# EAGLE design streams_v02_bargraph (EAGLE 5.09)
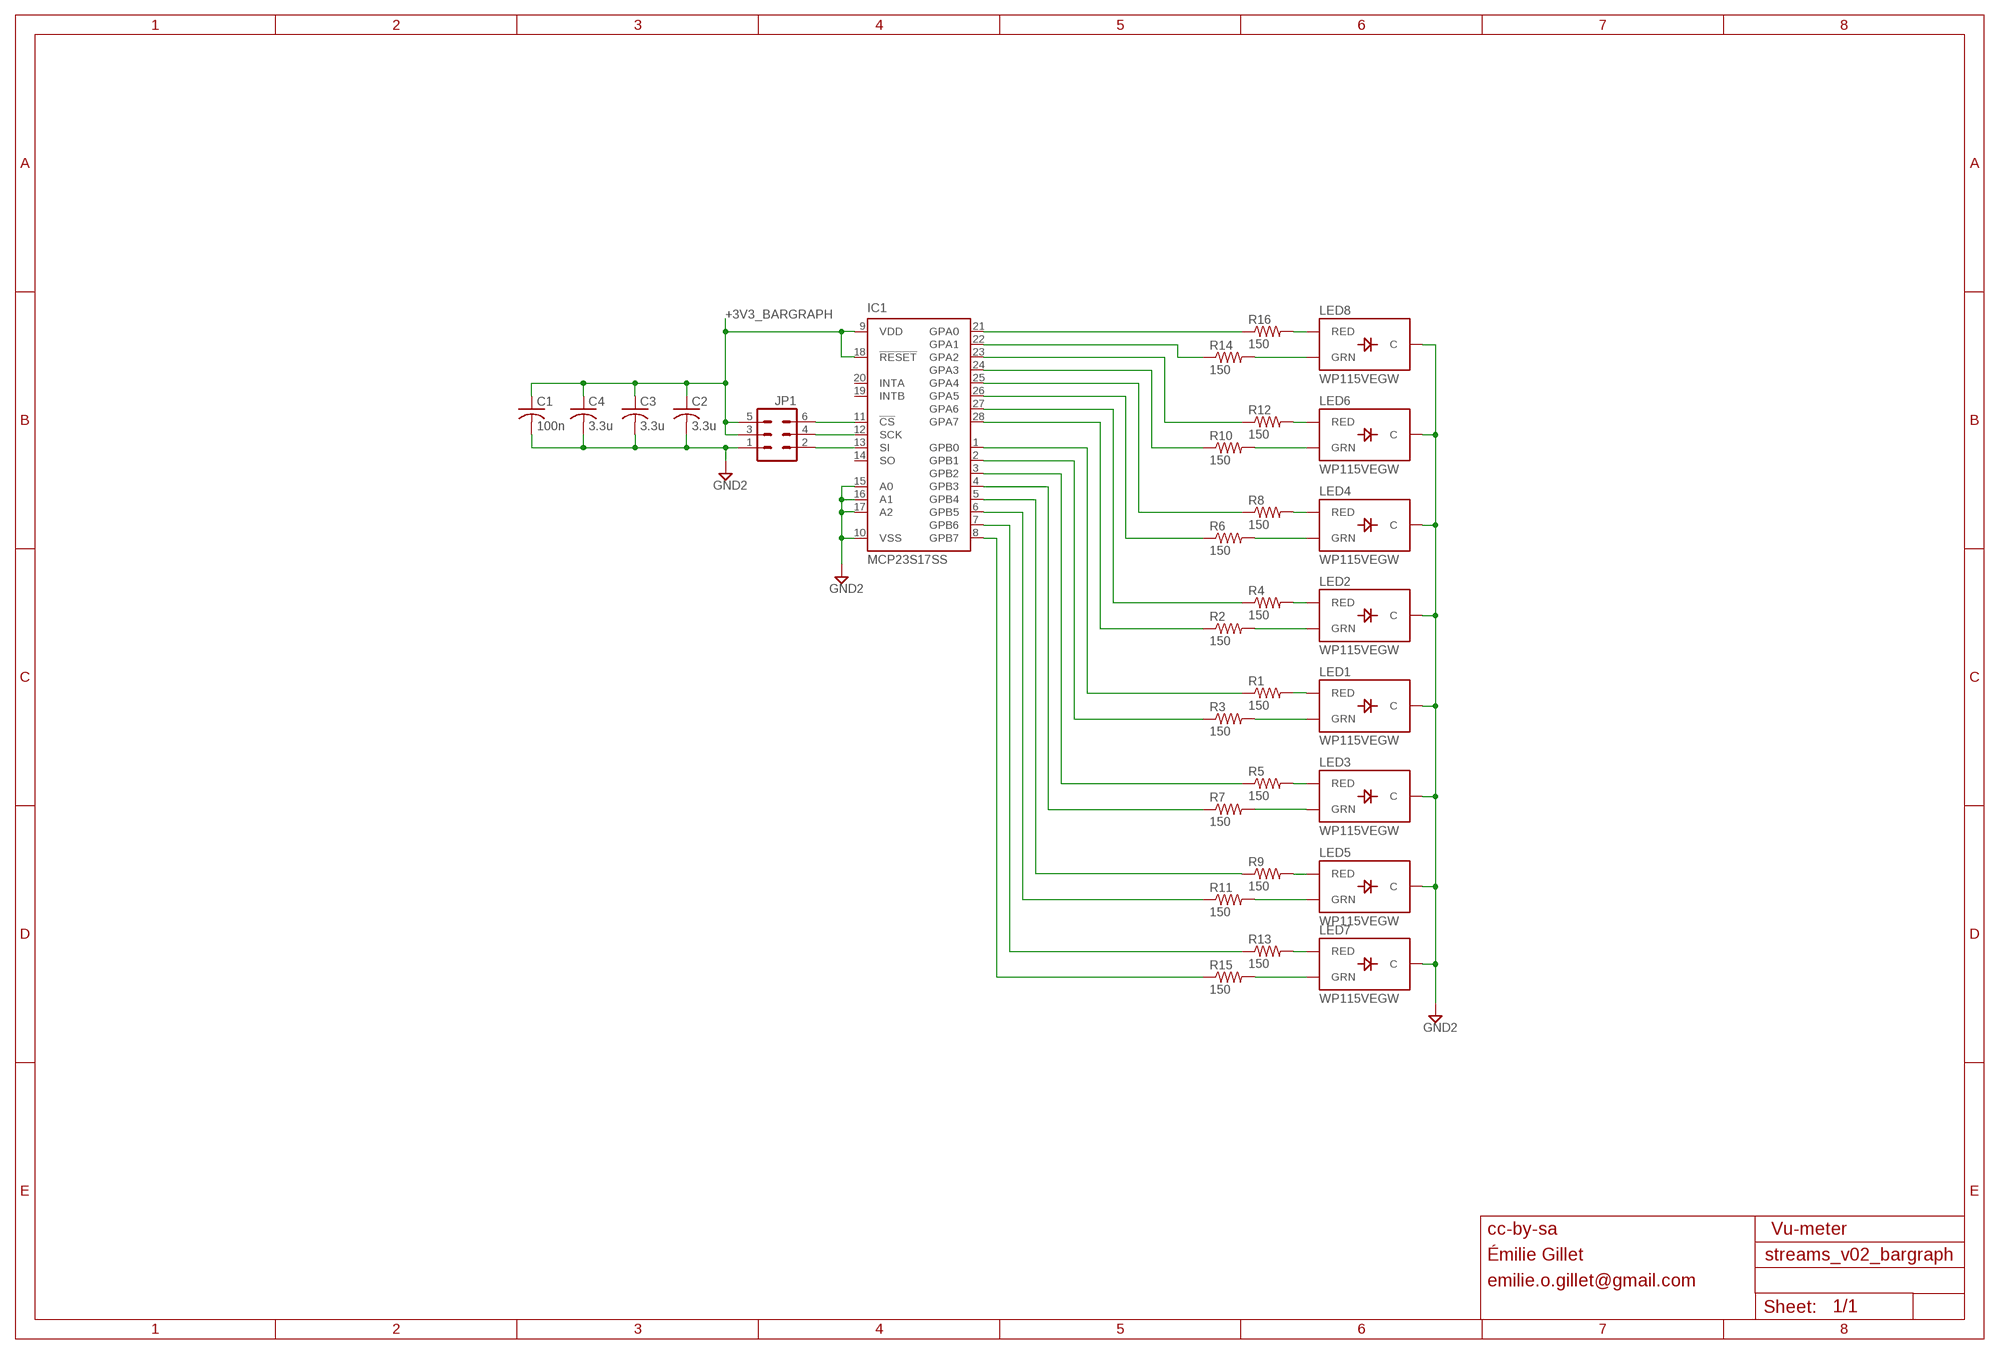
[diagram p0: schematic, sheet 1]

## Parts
C1  100n  C-USC0603  [C0603]
C2  3.3u  C-USC0603  [C0603]
C3  3.3u  C-USC0603  [C0603]
C4  3.3u  C-USC0603  [C0603]
IC1  MCP23S17SS  [SSOP28]
JP1  M03X2  [2X3]
LED1  WP115VEGW  LED-BICOLOR-THROUGHHOLE  [LED-BICOLOR-THROUGHHOLE]
LED2  WP115VEGW  LED-BICOLOR-THROUGHHOLE  [LED-BICOLOR-THROUGHHOLE]
LED3  WP115VEGW  LED-BICOLOR-THROUGHHOLE  [LED-BICOLOR-THROUGHHOLE]
LED4  WP115VEGW  LED-BICOLOR-THROUGHHOLE  [LED-BICOLOR-THROUGHHOLE]
LED5  WP115VEGW  LED-BICOLOR-THROUGHHOLE  [LED-BICOLOR-THROUGHHOLE]
LED6  WP115VEGW  LED-BICOLOR-THROUGHHOLE  [LED-BICOLOR-THROUGHHOLE]
LED7  WP115VEGW  LED-BICOLOR-THROUGHHOLE  [LED-BICOLOR-THROUGHHOLE]
LED8  WP115VEGW  LED-BICOLOR-THROUGHHOLE  [LED-BICOLOR-THROUGHHOLE]
R1  150  R-US_R0603  [R0603]
R2  150  R-US_R0603  [R0603]
R3  150  R-US_R0603  [R0603]
R4  150  R-US_R0603  [R0603]
R5  150  R-US_R0603  [R0603]
R6  150  R-US_R0603  [R0603]
R7  150  R-US_R0603  [R0603]
R8  150  R-US_R0603  [R0603]
R9  150  R-US_R0603  [R0603]
R10  150  R-US_R0603  [R0603]
R11  150  R-US_R0603  [R0603]
R12  150  R-US_R0603  [R0603]
R13  150  R-US_R0603  [R0603]
R14  150  R-US_R0603  [R0603]
R15  150  R-US_R0603  [R0603]
R16  150  R-US_R0603  [R0603]

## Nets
+3V3_BARGRAPH: C1.1 C2.1 C3.1 C4.1 IC1.9(VDD) IC1.18(!RESET) JP1.3 JP1.5
GND2: C1.2 C2.2 C3.2 C4.2 IC1.10(VSS) IC1.15(A0) IC1.16(A1) IC1.17(A2) JP1.1 LED1.2(C) LED2.2(C) LED3.2(C) LED4.2(C) LED5.2(C) LED6.2(C) LED7.2(C) LED8.2(C)
N$1: IC1.11(!CS) JP1.6
N$2: IC1.12(SCK) JP1.4
N$3: LED1.3(RED) R1.2
N$4: IC1.13(SI) JP1.2
N$12: LED1.1(GRN) R3.2
N$21: LED3.3(RED) R5.2
N$22: LED3.1(GRN) R7.2
N$30: LED5.3(RED) R9.2
N$31: LED5.1(GRN) R11.2
N$32: LED7.3(RED) R13.2
N$33: LED7.1(GRN) R15.2
N$34: LED8.3(RED) R16.2
N$35: LED8.1(GRN) R14.2
N$36: LED6.3(RED) R12.2
N$37: LED6.1(GRN) R10.2
N$38: LED4.3(RED) R8.2
N$39: LED4.1(GRN) R6.2
N$40: LED2.3(RED) R4.2
N$41: LED2.1(GRN) R2.2
N$42: IC1.27(GPA6) R4.1
N$44: IC1.28(GPA7) R2.1
N$48: IC1.1(GPB0) R1.1
N$49: IC1.2(GPB1) R3.1
N$50: IC1.21(GPA0) R16.1
N$52: IC1.22(GPA1) R14.1
N$53: IC1.23(GPA2) R12.1
N$54: IC1.24(GPA3) R10.1
N$55: IC1.25(GPA4) R8.1
N$57: IC1.26(GPA5) R6.1
N$58: IC1.3(GPB2) R5.1
N$59: IC1.4(GPB3) R7.1
N$60: IC1.5(GPB4) R9.1
N$61: IC1.6(GPB5) R11.1
N$62: IC1.7(GPB6) R13.1
N$63: IC1.8(GPB7) R15.1
Unconnected: IC1.14(SO) IC1.19(INTB) IC1.20(INTA)

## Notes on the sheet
- cc-by-sa | Vu-meter
- Émilie Gillet
- emilie.o.gillet@gmail.com

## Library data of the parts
C1-C4 = rcl:C-US: CAPACITOR, American symbol
IC1 = microchip:MCP23S17: http://ww1.microchip.com/downloads/en/DeviceDoc/21952a.pdf Source: http://ww1.microchip.com/downloads/en/DeviceDoc/21952a.pdf
JP1 = og-header:M03X2: PIN HEADER
LED1-LED8 = og-leds:LED-BICOLOR-THROUGHHOLE
R1-R16 = rcl:R-US_: RESISTOR, American symbol

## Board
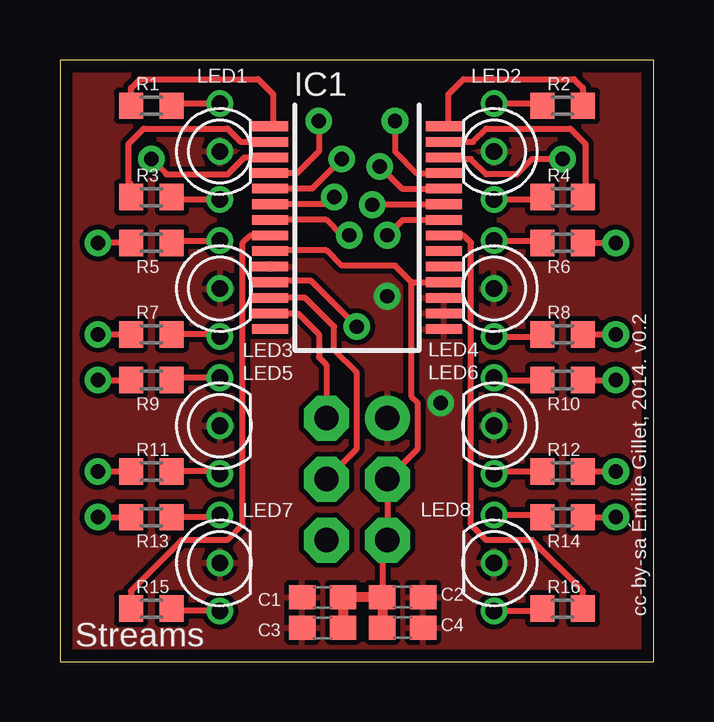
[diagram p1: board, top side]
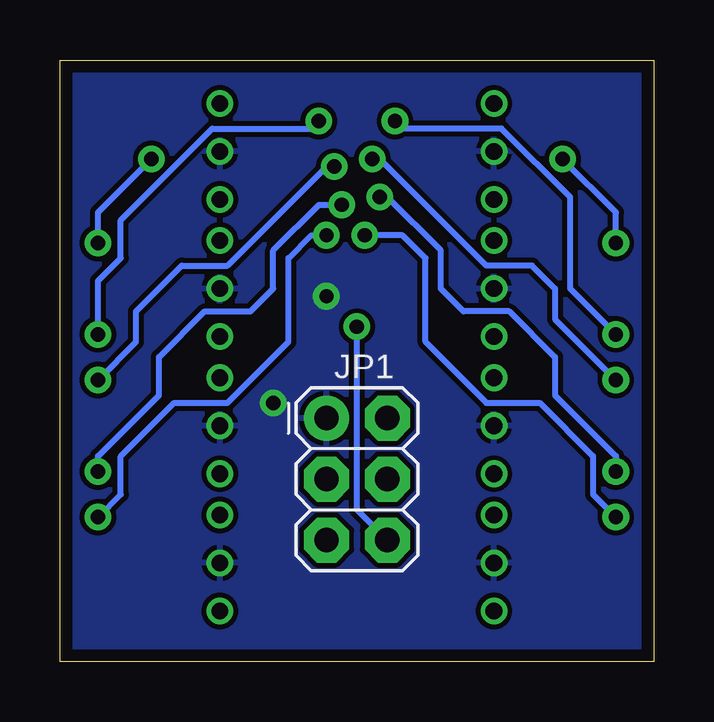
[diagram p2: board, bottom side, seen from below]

Size 24.77 x 25.08 mm. Coordinates in mm from the lower left corner, seen from the top.
Outline: 0,25.08 0,0 24.77,0 24.77,25.08 0,25.08
Copper layers (1*16): Top 0.035mm / dielectric 1.5mm / Bottom 0.035mm
Design rules "PCBCart-Standard": minimum track width 8mil, minimum drill 0.4mm, track to track 8mil, track to pad 8mil, pad to pad 8mil, via to via 8mil, smd to smd 8mil, copper to edge 20mil, drill to drill 8mil, minimum pad ring 8mil, minimum via ring 10mil, stop-mask expansion 3mil, vias tented up to drill 25mil, thermal gap 8mil

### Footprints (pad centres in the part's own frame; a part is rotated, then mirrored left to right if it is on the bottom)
C0603 = smd 1.1 x 1: 1 -0.85,0; 2 0.85,0
SSOP28 = smd 0.4 x 1.5: 1 -4.225,-3.625; 2 -3.575,-3.625; 3 -2.925,-3.625; 4 -2.275,-3.625; 5 -1.625,-3.625; 6 -0.975,-3.625; 7 -0.325,-3.625; 8 0.325,-3.625; 9 0.975,-3.625; 10 1.625,-3.625; 11 2.275,-3.625; 12 2.925,-3.625; 13 3.575,-3.625; 14 4.225,-3.625; 15 4.225,3.625; 16 3.575,3.625; 17 2.925,3.625; 18 2.275,3.625; 19 1.625,3.625; 20 0.975,3.625; 21 0.325,3.625; 22 -0.325,3.625; 23 -0.975,3.625; 24 -1.625,3.625; 25 -2.275,3.625; 26 -2.925,3.625; 27 -3.575,3.625; 28 -4.225,3.625
2X3 = drill 1.016 pad 1.88 round: 1 -2.54,-1.27 | drill 1.016 pad 1.88 octagon: 2 -2.54,1.27; 3 0,-1.27; 4 0,1.27; 5 2.54,-1.27; 6 2.54,1.27
LED-BICOLOR-THROUGHHOLE = drill 0.7 round: 1 -2,0; 2 0,0; 3 2,0
R0603 = smd 1 x 1.1: 1 -0.85,0; 2 0.85,0

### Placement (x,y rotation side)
C1  10.95,2.7 180 top
C2  14.29,2.7 0 top
C3  10.95,1.43 180 top
C4  14.29,1.43 0 top
IC1  12.38,18.1 270 top
JP1  12.38,7.62 270 bottom
LED1  6.67,21.27 90 top
LED2  18.1,21.27 270 top
LED3  6.67,15.56 90 top
LED4  18.1,15.56 270 top
LED5  6.67,9.84 90 top
LED6  18.1,9.84 270 top
LED7  6.67,4.13 90 top
LED8  18.1,4.13 270 top
R1  3.81,23.18 0 top
R2  20.95,23.18 180 top
R3  3.81,19.37 0 top
R4  20.95,19.37 180 top
R5  3.81,17.46 0 top
R6  20.95,17.46 180 top
R7  3.81,13.65 0 top
R8  20.95,13.65 180 top
R9  3.81,11.75 0 top
R10  20.95,11.75 180 top
R11  3.81,7.94 0 top
R12  20.95,7.94 180 top
R13  3.81,6.03 0 top
R14  20.95,6.03 180 top
R15  3.81,2.22 0 top
R16  20.95,2.22 180 top

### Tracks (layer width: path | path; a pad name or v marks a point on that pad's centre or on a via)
+3V3_BARGRAPH
  Top 0.254: IC1.9 8.78,17.14 11.11,17.14 11.75,16.51 13.97,16.51 14.66,15.82 | 14.66,15.82 IC1.18 | 14.66,15.82 14.66,11.06 14.92,10.79 14.92,8.89 JP1.3 JP1.5 13.44,4.87 C2.1
  Top 0.406: C3.1 C1.1 C2.1 | C2.1 | C2.1 C4.1
GND2  (via drill 0.6)
  other vias: 13.65,15.24 15.88,10.79
  pour Bottom: 24.77,25.08 24.77,0 0,0 0,25.08
  pour Top: 0,25.08 0,0 24.77,0 24.77,25.08
N$1  (via drill 0.6)
  Top 0.254: IC1.11 8.81,15.88 10.48,15.88 v12.38,13.97
  Bottom 0.254: v12.38,13.97 12.38,6.35 JP1.6
N$2
  Top 0.254: JP1.4 12.38,8.89 12.38,12.07 11.43,13.02 11.43,13.97 10.23,15.17 IC1.12
N$3
  Top 0.254: R1.2 4.75,23.27 LED1.3
N$4
  Top 0.254: JP1.2 11.11,12.38 10.8,12.7 10.8,13.65 9.92,14.52 IC1.13
N$12
  Top 0.254: R3.2 4.75,19.27 LED1.1
N$21
  Top 0.254: R5.2 4.75,17.56 LED3.3
N$22
  Top 0.254: LED3.1 6.57,13.65 R7.2
N$30
  Top 0.254: R9.2 4.75,11.84 LED5.3
N$31
  Top 0.254: LED5.1 6.57,7.94 R11.2
N$32
  Top 0.254: LED7.3 6.57,6.03 R13.2
N$33
  Top 0.254: R15.2 4.75,2.13 LED7.1
N$34
  Top 0.254: R16.2 20.01,2.13 LED8.3
N$35
  Top 0.254: R14.2 20.01,6.13 LED8.1
N$36
  Top 0.254: LED6.3 18.19,7.94 R12.2
N$37
  Top 0.254: LED6.1 18.19,11.75 R10.2
N$38
  Top 0.254: R8.2 20.01,13.56 LED4.3
N$39
  Top 0.254: R6.2 20.01,17.56 LED4.1
N$40
  Top 0.254: R4.2 20.01,19.27 LED2.3
N$41
  Top 0.254: R2.2 20.01,23.27 LED2.1
N$42
  Top 0.254: R4.1 21.91,19.47 21.91,21.59 21.27,22.23 17.78,22.23 17.23,21.67 IC1.27
N$44
  Top 0.254: IC1.28 16.19,22.51 16.19,23.65 16.83,24.29 21.43,24.29 21.8,23.92 R2.1
N$48
  Top 0.254: IC1.1 8.89,22.46 8.89,23.65 8.25,24.29 3.33,24.29 2.96,23.92 R1.1
N$49
  Top 0.254: IC1.2 7.54,21.67 6.99,22.23 3.49,22.23 2.86,21.59 2.86,20 2.96,19.9 R3.1
N$50
  Top 0.254: IC1.21 16.01,17.78 16.83,17.78 17.15,17.46 17.15,5.71 17.78,5.08 19.69,5.08 21.8,2.96 R16.1
N$52  (via drill 0.6)
  Top 0.254: R14.1 v23.18,6.03 | v13.65,17.78 14.3,18.42 IC1.22
  Bottom 0.254: v23.18,6.03 22.22,6.99 22.22,8.57 20,10.79 17.78,10.79 15.24,13.34 15.24,16.83 14.29,17.78 v13.65,17.78
N$53  (via drill 0.6)
  Top 0.254: R12.1 v23.18,7.94 | v13.02,19.05 13.04,19.07 IC1.23
  Bottom 0.254: v13.02,19.05 13.97,19.05 15.88,17.14 15.88,15.56 16.83,14.61 18.73,14.61 20.64,12.7 20.64,11.11 23.18,8.57 v23.18,7.94
N$54  (via drill 0.6)
  Top 0.254: R10.1 v23.18,11.75 | v13.34,20.64 14.25,19.72 IC1.24
  Bottom 0.254: v13.34,20.64 13.65,20.64 17.78,16.51 19.69,16.51 21.59,14.61 21.59,13.34 v23.18,11.75
N$55  (via drill 0.6)
  Top 0.254: v13.97,22.54 13.97,21.27 14.87,20.37 IC1.25 | R8.1 v23.18,13.65
  Bottom 0.254: v23.18,13.65 23.18,15.88 22.22,16.83 22.22,18.41 18.41,22.23 14.29,22.23 v13.97,22.54
N$57  (via drill 0.6)
  Top 0.254: IC1.26 16.07,20.96 17.15,20.96 17.78,20.32 19.05,20.32 19.69,20.96 v20.95,20.96 | R6.1 v23.18,17.46
  Bottom 0.254: v20.95,20.96 23.18,18.73 v23.18,17.46
N$58  (via drill 0.6)
  Top 0.254: R5.1 v1.59,17.46 | v3.81,20.96 4.44,20.32 6.99,20.32 7.69,21.02 IC1.3
  Bottom 0.254: v1.59,17.46 1.59,18.73 v3.81,20.96
N$59  (via drill 0.6)
  Top 0.254: v1.59,13.65 R7.1 | v10.8,22.54 10.8,21.27 9.9,20.37 IC1.4
  Bottom 0.254: v1.59,13.65 3.49,15.56 3.49,19.37 6.35,22.23 10.48,22.23 v10.8,22.54
N$60  (via drill 0.6)
  Top 0.254: v1.59,11.75 R9.1 | v11.75,20.96 10.52,19.72 IC1.5
  Bottom 0.254: v1.59,11.75 4.13,14.29 4.13,15.56 5.08,16.51 6.99,16.51 11.43,20.96 v11.75,20.96
N$61  (via drill 0.6)
  Top 0.254: v1.59,7.94 R11.1 | v11.43,19.37 11.13,19.07 IC1.6
  Bottom 0.254: v1.59,7.94 1.59,8.57 4.13,11.11 4.13,12.7 6.03,14.61 7.94,14.61 8.89,15.56 8.89,17.14 11.11,19.37 v11.43,19.37
N$62  (via drill 0.6)
  Top 0.254: v1.59,6.03 R13.1 | v12.06,17.78 11.75,17.78 11.1,18.42 IC1.7
  Bottom 0.254: v1.59,6.03 2.54,6.99 2.54,8.57 4.76,10.79 6.99,10.79 9.53,13.34 9.53,16.83 10.48,17.78 v12.06,17.78
N$63
  Top 0.254: IC1.8 8.75,17.78 7.94,17.78 7.62,17.46 7.62,5.71 6.99,5.08 5.08,5.08 2.96,2.96 R15.1

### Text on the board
tNames: cc-by-sa Émilie Gillet, 2014. v0.2 | Streams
